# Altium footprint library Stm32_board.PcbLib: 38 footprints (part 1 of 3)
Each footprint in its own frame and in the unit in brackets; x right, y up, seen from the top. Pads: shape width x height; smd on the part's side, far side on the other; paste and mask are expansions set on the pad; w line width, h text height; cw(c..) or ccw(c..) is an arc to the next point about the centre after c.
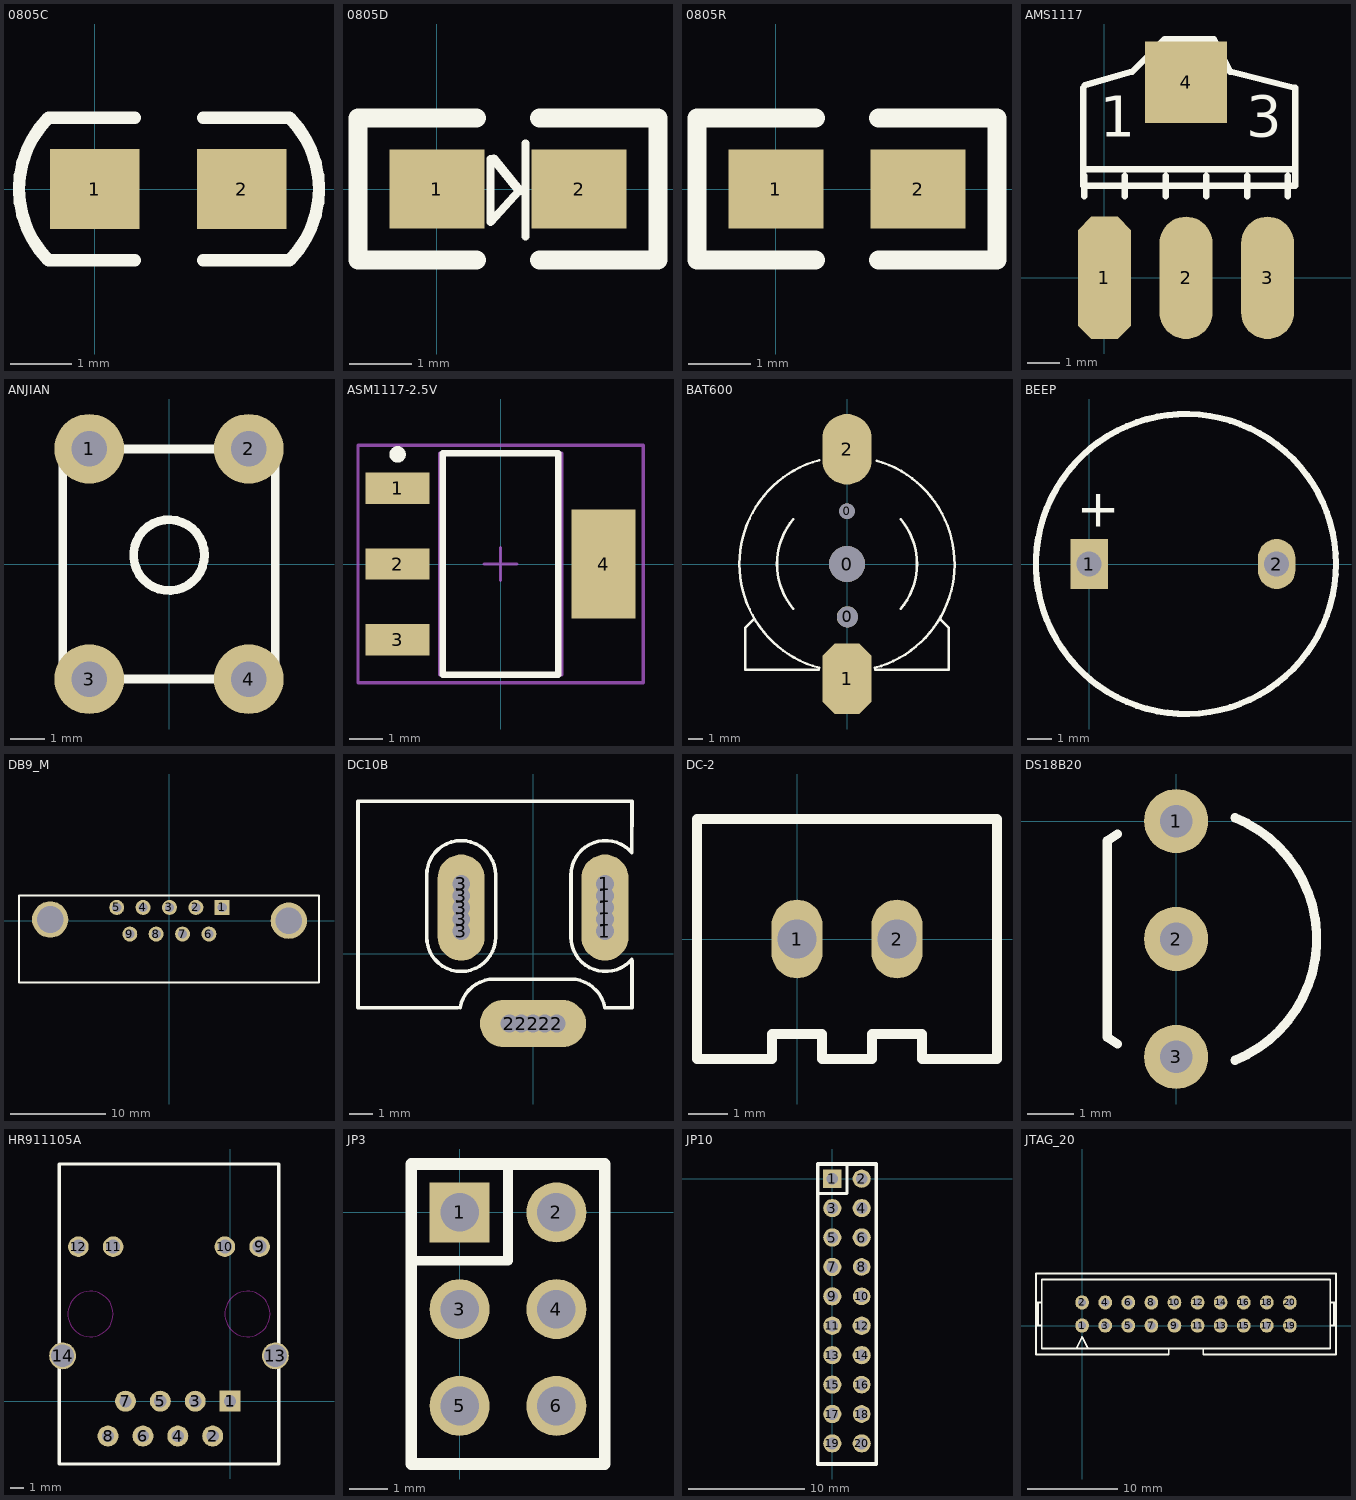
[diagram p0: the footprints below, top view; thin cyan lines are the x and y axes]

## 0805C [mm]
pads (2):
  rect 1.45x1.3 smd: 1(0,0) 2(2.379,0)
Top Overlay:
  lines w0.2: 0.65,-1.15 -0.75,-1.15 cw(c0.4,0) -0.75,1.15 0.65,1.15 ; 1.75,-1.15 3.15,-1.15 ccw(c2,0) 3.15,1.15 1.75,1.15

## 0805D [mil]
pads (2):
  rect 60x50 smd: 1(0,0) 2(90,0)
Top Overlay:
  lines w5: 34,19 34,-21 52,-1 ; 56,-30 56,29
  lines w6: 36,19 52,-1
  lines w12: 25,-45 -50,-45 -50,45 25,45 ; 65,-45 140,-45 140,45 65,45

## 0805R [mil]
pads (2):
  rect 60x50 smd: 1(0,0) 2(90,0)
Top Overlay:
  lines w12: 25,-45 -50,-45 -50,45 25,45 ; 65,-45 140,-45 140,45 65,45

## AMS1117 [mil]
pads (4):
  oct 65x150 smd: 1(0,0)
  oval 65x150 smd: 2(100,0) 3(200,0)
  rect 100x100 smd: 4(100,240)
Top Overlay:
  lines w7.87: -26,233 -26,133 ; -25,100 -25,125 ; -24.33,236.33 34,253 74,293 134,293 154,253 234,233 234,113 ; 25,100 25,125 ; 75,100 75,125 ; 125,100 125,125 ; 175,100 175,125 ; 225,100 225,125 ; -26,133 234,133 234,113 ; -26,133 -26,113 234,113
  text "3" at 174,173 h50
  text "1" at -6,173 h50

## ANJIAN [mil]
pads (4):
  round 78.74 hole 40: 1(-90,130) 2(90,130) 3(-90,-130) 4(90,-130)
Top Overlay:
  circle w10: c0,10 r40
  lines w10: -120,-130 -120,130 120,130 120,-130 -120,-130

## ASM1117-2.5V [mm] "SOT223, 4-Leads, Body 6.7x7.3mm (max), Pitch 2.30mm, IPC Medium Density"
height 1.8
pads (4):
  rect 1.95x0.95 smd: 1(-3.125,2.3) 2(-3.125,0) 3(-3.125,-2.3)
  rect 1.95x3.3 smd: 4(3.125,0)
Top Overlay:
  circle w0.25: c-3.125,3.325 r0.125
  lines w0.2: -1.75,-3.355 -1.75,3.355 1.75,3.355 1.75,-3.355 -1.75,-3.355
Mechanical 13:
  lines w0.1: -1.855,-3.355 -1.855,3.355 1.855,3.355 1.855,-3.355 -1.855,-3.355
Mechanical 15:
  lines w0.1: -0.5,0 0.5,0 ; 0,-0.5 0,0.5 ; -4.325,-3.605 -4.325,3.605 4.325,3.605 4.325,-3.605 -4.325,-3.605
3D body: height 1.8, standoff 0.06, extent -1.855,-3.355 1.855,3.355

## BAT600 [mm]
pads (5):
  round 2.54 hole 2.54: 0(-0.012,0)
  round 1.1 hole 1.1: 0(-0.012,3.75)
  round 1.5 hole 1.5: 0(0.012,-3.75)
  oct 3.5x5 smd: 1(-0.012,-8.128)
  oval 3.5x5 smd: 2(-0.012,8.128)
Top Overlay:
  lines w0.178: -6.613,-3.9 -7.213,-4.5 -7.213,-7.5 -2.013,-7.5 ; -3.827,-3.169 cw(c-0.012,0) -3.825,3.172 ; -1.976,-7.363 cw(c-0.012,0) -7.632,0 cw(c-0.012,0) -1.976,7.363 ; 1.951,-7.363 ccw(c-0.012,0) 2.081,7.327 ; 1.987,-7.5 7.187,-7.5 7.187,-4.5 6.612,-3.925 ; 3.797,-3.175 ccw(c-0.012,0) 3.8,3.172

## BEEP [mil]
pads (2):
  rect 60x80 hole 40: 1(0,0)
  oval 60x80 hole 40: 2(300,0)
Top Overlay:
  circle w10: c155,0 r240
  text "+" at -20,60 h60

## DB9_M [mil]
pads (11):
  rect 62x62 hole 38: 1(218,55)
  round 62 hole 38: 2(109,55) 3(0,55) 4(-109,55) 5(-218,55) 6(163,-55) 7(54,-55) 8(-55,-55) 9(-164,-55)
  round 150 hole 110: ""(-493,5) ""(493,0)
Top Overlay:
  lines w8: -622,-255 -622,104 618,104 618,-255 -622,-255

## DC10B [mil]
pads (15):
  round 45 hole 30: 1(122.05,38.43) 1(122.05,58.43) 1(122.05,98.43) 1(122.05,118.43) 2(-40,-118.43) 2(-20,-118.43) 2(20,-118.43) 2(40,-118.43) 3(-122.05,38.43) 3(-122.05,58.43) 3(-122.05,98.43) 3(-122.05,118.43)
  oval 80x180 hole 30: 1(122.05,78.43) 3(-122.05,78.43)
  oval 180x80 hole 30: 2(0,-118.43)
Top Overlay:
  lines w6: -128.05,-91.57 -297.05,-91.57 -297.05,258.43 167.95,258.43 167.78,171.04 ccw(c122.95,133.43) 64.43,133.43 64.43,28.43 ccw(c122.95,28.43) 167.78,-9.19 ; -123.68,-91.41 cw(c-66.05,-101.57) -66.05,-43.05 63.95,-43.05 cw(c63.95,-101.57) 121.59,-91.41 ; 122.95,-91.57 167.95,-91.57 167.95,-11.57 ; -180.57,28.43 ccw(c-122.05,28.43) -63.52,28.43 -63.52,133.42 -63.52,133.43 ccw(c-122.05,133.43) -180.57,133.43 -180.57,133.42 -180.57,28.43

## DC-2 [mm]
pads (2):
  oval 1.3x2 hole 1: 1(0,0) 2(2.54,0)
Top Overlay:
  lines w0.254: -2.54,-2.032 -2.54,1.651 ; -2.54,1.397 -2.54,1.905 ; -2.54,-3.048 -0.635,-3.048 -0.635,-2.413 0.635,-2.413 0.635,-3.048 1.905,-3.048 1.905,-2.413 3.175,-2.413 3.175,-3.048 5.08,-3.048 5.08,3.048 -2.54,3.048 -2.54,-3.048

## DS18B20 [mm]
pads (3):
  round 1.38 hole 0.7: 1(0,0) 2(0,-2.54) 3(0,-5.08)
Top Overlay:
  lines w0.2: -1.263,-4.803 -1.482,-4.657 -1.482,-0.423 -1.263,-0.277 ; 1.266,-5.15 ccw(c0.212,-2.54) 1.266,0.07

## HR911105A [mil]
pads (14):
  rect 60x60 hole 35: 1(0,0)
  round 60 hole 35: 2(-50,-100) 3(-100,0) 4(-150,-100) 5(-200,0) 6(-250,-100) 7(-300,0) 8(-350,-100)
  round 59.06 hole 40.16: 9(84.65,442.91) 12(-435.04,442.91)
  round 59.05 hole 40.16: 10(-15.2,442.91) 11(-335.2,442.91)
  round 76.93 hole 64.96: 13(129.92,130) 14(-480.31,130)
Top Overlay:
  lines w10: -490.16,-180 -175.2,-180 139.76,-180 139.76,680 -175.2,680 -490.16,680 -490.16,-180
Keep-Out Layer:
  circle w2: c-400.16,250 r64.96
  circle w2: c49.84,250 r64.96

## JP3 [mil]
pads (6):
  rect 62x62 hole 40: 1(0,0)
  round 62 hole 40: 2(100,0) 3(0,-100) 4(100,-100) 5(0,-200) 6(100,-200)
Top Overlay:
  lines w10: -50,-50 50,-50 50,50
  lines w12: -50,-260 150,-260 150,-75 150,50 -50,50 -50,-75 -50,-250 -50,-260

## JP10 [mil]
pads (20):
  rect 62x62 hole 40: 1(0,0)
  round 62 hole 40: 2(100,0) 3(0,-100) 4(100,-100) 5(0,-200) 6(100,-200) 7(0,-300) 9(0,-400) 11(0,-500) 12(100,-500) 13(0,-600) 14(100,-600) 15(0,-700) 17(0,-800) 19(0,-900) 20(100,-900)
  round 60 hole 40: 8(100,-300) 10(100,-400) 16(100,-700) 18(100,-800)
Top Overlay:
  lines w10: -50,-50 50,-50 50,50
  lines w12: -50,-455 -50,-360 -50,-325 -50,-75 -50,50 150,50 150,-75 150,-325 150,-360 150,-455 ; -50,-352 -50,-477 -50,-970 150,-970 150,-477 150,-352

## JTAG_20 [mm]
pads (20):
  oval 1.5x1.575 hole 0.9: 1(0,0) 2(0,2.54) 3(2.54,0) 4(2.54,2.54) 5(5.08,0) 6(5.08,2.54) 7(7.62,0) 8(7.62,2.54) 9(10.16,0) 10(10.16,2.54) 11(12.7,0) 12(12.7,2.54) 13(15.24,0) 14(15.24,2.54) 15(17.78,0) 16(17.78,2.54) 17(20.32,0) 18(20.32,2.54) 19(22.86,0) 20(22.86,2.54)
Top Overlay:
  lines w0.203: -5.08,0 -4.445,0 ; -5.08,2.54 -4.445,2.54 ; -4.868,0 -4.868,2.54 ; -0.635,-2.54 0,-1.27 0.635,-2.54 ; 2.805,-3.175 9.525,-3.175 9.525,-2.54 ; 3.175,-3.175 -5.08,-3.175 -5.08,5.715 27.94,5.715 27.94,-3.175 19.685,-3.175 13.335,-3.175 13.335,-2.54 ; 27.305,0 27.94,0 ; 27.305,2.54 27.94,2.54 ; 27.728,0 27.728,2.54 ; 9.525,-2.54 13.335,-2.54 ; 9.525,-2.54 -4.445,-2.54 -4.445,5.08 27.305,5.08 27.305,-2.54 13.335,-2.54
